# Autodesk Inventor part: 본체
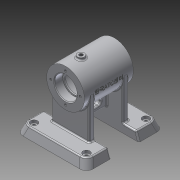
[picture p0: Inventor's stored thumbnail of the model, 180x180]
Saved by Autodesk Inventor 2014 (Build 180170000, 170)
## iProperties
Created: 2016-07
Part Number: 본체
Material: 알루미늄 6061
Document SubType Name: Modeling
Designer: Administrator
Density: 2.71 g/cm^3
Appearance: 알루미늄 - 평지
Mass: 499.112 g
Surface Area: 538.836 cm^2
Volume: 184.174 cm^3
Author: Administrator
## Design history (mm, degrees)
sketch "스케치1"
  geometry: C1 r 27 at (0, 70); 1 further point
  constraints: 1 centre point, 1 vertical alignment
  dimensions: "d0" = 54 diameter of C1; "d1" = 70 distance of C1.centre point (0, 0)
extrude "돌출1" new body sketch "스케치1" stored distance "d2" = 70; taper "d3" = 0 deg
hole "구멍1" diameter "d6" = 28; stored, may be unused: countersink angle "d10" = 90 deg, drill point angle "d12" = 0 deg; dims "d4" = 10, "d5" = 10, "d7" = 6, "d8" = 32, "d9" = 12, "d11" = 14
hole "구멍2" diameter "d15" = 28; stored, may be unused: countersink angle "d19" = 90 deg, drill point angle "d21" = 0 deg; dims "d13" = 10, "d14" = 10, "d16" = 6, "d17" = 32, "d18" = 12, "d20" = 14
node "작업 평면1"
sketch "스케치2"
  geometry: L1 (-27, -35)-(27, -35) reference; C1 r 5 at (0, -13); 1 further point
  constraints: 1 centre point, 1 vertical alignment
  dimensions: "d23" = 22 distance from line of C1.centre L1; "d24" = 10 diameter of C1
extrude "돌출2" join sketch "스케치2" stored distance "d25" = 70; taper "d26" = 0 deg
sketch "스케치3"
  geometry: C1 r 16 at (0, 0) reference; C2 r 27 at (0, 0) reference; A1 r 21 centre (0, 0) between (0, 21) and (21, 0); 3 further points
  constraints: 4 point on circle, 2 horizontal alignment, 2 vertical alignment, 1 centre point, 1 coincident
  dimensions: "d27" = 42 diameter of A1
hole "구멍3" sketch "스케치3" at (0, 21), (0, -21), (-21, 0), (21, 0) diameter "d28" = 3.242; stored, may be unused: countersink angle "d32" = 90 deg, drill point angle "d34" = 118 deg; dims "d29" = 8, "d30" = 32, "d31" = 12, "d33" = 10
hole "구멍4" diameter "d37" = 44; stored, may be unused: countersink angle "d41" = 90 deg, drill point angle "d43" = 0 deg; dims "d35" = 10, "d36" = 10, "d38" = 8, "d39" = 32, "d40" = 12, "d42" = 42
fillet "모깎기1" dims "d44" = 0.3
fillet "모깎기2" dims "d45" = 3
hole "구멍5" diameter "d48" = 5.188; stored, may be unused: countersink angle "d52" = 90 deg, drill point angle "d54" = 0 deg; dims "d46" = 10, "d47" = 10, "d49" = 20, "d50" = 32, "d51" = 12, "d53" = 42
fillet "모깎기3" dims "d55" = 2
node "작업 평면2"
sketch "스케치4"
  geometry: L1 (-35, 27)-(35, 27) reference; L2 (-35, 27)-(-35, -27) reference; 2 further points
  constraints: 1 other
  dimensions: "d56" = 70 distance of point (0, -70) point (0, 0); "d57" = 27 distance from line of point (0, 0) L1 (derived); "d58" = 35 distance from line of point (0, 0) L2
feature "엠보싱1" sketch "스케치4" dims "d0" = 54, "d59" = 0.5, "d60" = 0
sketch "스케치5"
  geometry: L1 (-50, -55)-(50, -55); L2 (50, -55)-(50, 55); L3 (50, 55)-(-50, 55); L4 (-50, 55)-(-50, -55); L5 (-50, -55)-(50, 55); L6 (50, -55)-(-50, 55); 1 further point
  constraints: 12 end point, 2 midpoint, 2 parallel, 1 horizontal, 1 perpendicular
  dimensions: "d61" = 100 distance of L3.end L2.end; "d62" = 110 distance of L2.end L1.end
extrude "돌출3" join sketch "스케치5" distance "d63" = 12; taper "d64" = -20 deg
sketch "스케치6"
  geometry: L1 (50, -20)-(-50, -20); L2 (-50, -20)-(-50, 20); L3 (-50, 20)-(50, 20); L4 (50, 20)-(50, -20); L5 (50, -20)-(-50, 20); L6 (-50, -20)-(50, 20); L7 (50, 55)-(-50, 55) reference; L8 (-50, -55)-(50, -55) reference; L9 (50, -55)-(50, 55) reference; L10 (-50, 55)-(-50, -55) reference; 3 further points
  constraints: 12 end point, 3 midpoint, 2 parallel, 1 coincident, 1 horizontal, 1 perpendicular
  dimensions: "d65" = 110 distance between parallel lines of L7 L8 (derived); "d66" = 100 distance between parallel lines of L9 L10 (derived); "d67" = 35 distance between parallel lines of L3 L7; "d68" = 100 distance of L2.end L3.end
extrude "돌출4" cut sketch "스케치6" distance "d69" = 12; taper "d70" = 0 deg
sketch "스케치7"
  geometry: L1 (45.632, -20)-(-45.632, -20) reference; L2 (-27, -20)-(27, -20); L3 (27, -20)-(27, -28); L4 (27, -28)-(-27, -28); L5 (-27, -28)-(-27, -20); 2 further points
  constraints: 8 end point, 2 parallel, 1 collinear, 1 horizontal, 1 midpoint, 1 perpendicular, 1 vertical alignment
  dimensions: "d71" = 8 distance between parallel lines of L4 L1; "d72" = 54 distance of L3.end L4.end
extrude "돌출5" join sketch "스케치7" stored distance "d73" = 12; taper "d74" = 0 deg
node "작업 평면3"
sketch "스케치8"
  geometry: L1 (-4, -20)-(4, -20); L2 (4, -20)-(4, 20); L3 (4, 20)-(-4, 20); L4 (-4, 20)-(-4, -20); L5 (-4, -20)-(4, 20); L6 (4, -20)-(-4, 20); L7 (50, 20)-(-50, 20) reference; 1 further point
  constraints: 12 end point, 2 midpoint, 2 parallel, 1 collinear, 1 horizontal, 1 perpendicular
  dimensions: "d76" = 8 distance between parallel lines of L2 L4
extrude "돌출6" join sketch "스케치8" stored distance "d77" = 12; taper "d78" = 0 deg
sketch "스케치9"
  geometry: L1 (50, 20)-(50, 55) reference; L2 (-50, 55)-(-50, 20) reference; L3 (-37.5, -42.5)-(37.5, -42.5); L4 (37.5, -42.5)-(37.5, 42.5); L5 (37.5, 42.5)-(-37.5, 42.5); L6 (-37.5, 42.5)-(-37.5, -42.5); L7 (-37.5, -42.5)-(37.5, 42.5); L8 (37.5, -42.5)-(-37.5, 42.5); 5 further points
  constraints: 12 end point, 4 coincident, 2 midpoint, 2 parallel, 1 horizontal, 1 perpendicular
  dimensions: "d79" = 100 distance between parallel lines of L1 L2 (derived); "d80" = 75 distance of L5.end L4.end; "d81" = 85 distance of L4.end L3.end
hole "구멍6" sketch "스케치9" at (-37.5, 42.5), (37.5, 42.5), (37.5, -42.5), (-37.5, -42.5) diameter "d82" = 6; stored, may be unused: countersink angle "d86" = 90 deg, drill point angle "d88" = 0 deg; dims "d83" = 20, "d84" = 10, "d85" = 4, "d87" = 42
fillet "모깎기4" dims "d89" = 10
fillet "모깎기5" dims "d90" = 2
fillet "모깎기6" dims "d91" = 2
fillet "모깎기7" dims "d92" = 2
sketch "스케치10"
  geometry: L1 (0, 36)-(0, 0) reference; L2 (-8, 10)-(-8, 26); L3 (-4.5, 10)-(-4.5, 26); L4 (-11.5, 26)-(-11.5, 10); L5 (24, 40)-(24, 63.603) reference; A1 r 3.5 centre (-8, 10) between (-11.5, 10) and (-4.5, 10); A2 r 3.5 centre (-8, 26) between (-4.5, 26) and (-11.5, 26); 2 further points
  constraints: 8 end point, 4 point on circle, 4 tangent, 2 centre point, 2 parallel, 1 horizontal alignment, 1 midpoint
  dimensions: "d93" = 32 distance between parallel lines of L2 L5; "d94" = 23 dimension on A2 A1; "d95" = 3.5 radius of A2
extrude "돌출7" cut sketch "스케치10" stored distance "d96" = 12; taper "d97" = 0 deg; dims "d36" = 10
fillet "모깎기8" dims "d98" = 2
sketch "스케치11"
  geometry: L1 (0, 70)-(15.898, 44.559); L2 (0, 70)-(0, 43); 2 further points
  constraints: 4 end point, 1 coincident, 1 vertical, 1 vertical alignment, 1 other
  dimensions: "d99" = 32 deg angle of L2 L1; "d100" = 30 distance of L1.start L1.end
node "작업 평면4"
sketch "스케치12"
  geometry: C1 r 6 at (0, 0); 2 further points
  constraints: 1 centre point, 1 coincident
  dimensions: "d101" = 12 diameter of C1
extrude "돌출8" join sketch "스케치12" stored distance "d102" = 12; taper "d103" = 0 deg
hole "구멍7" diameter "d106" = 5.188; stored, may be unused: countersink angle "d110" = 90 deg, drill point angle "d112" = 0 deg; dims "d104" = 10, "d105" = 10, "d107" = 30, "d108" = 10, "d109" = 4, "d111" = 30
fillet "모깎기9" dims "d113" = 2
chamfer "모따기1" distance "d114" = 1; stored, may be unused: second distance "d115" = 2, angle "d116" = 45 deg
node "솔리드1"
mirror "대칭1"
mirror "대칭2"
other parameters: "d75" = 22
